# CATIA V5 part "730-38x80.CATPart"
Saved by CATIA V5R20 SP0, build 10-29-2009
Part number: 730-38x80
Definition: NONE
Nomenclature: 730-38x80
Source: Unknown
Description: 730-38x80
Bounding box of the stored display mesh (mm): x -23 to 23, y -22.5 to 22.5, z 0 to 80
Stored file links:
  C:\Users\Utente\Desktop\IO LAVORO\3D X SITO CF\X SITO\730\730-38x80.CATPart
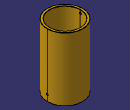
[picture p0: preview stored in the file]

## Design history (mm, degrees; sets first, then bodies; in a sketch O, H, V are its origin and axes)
Body1 "730-38x80" (main body)
  Solid1: solid without history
